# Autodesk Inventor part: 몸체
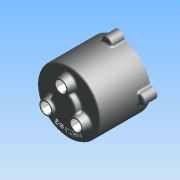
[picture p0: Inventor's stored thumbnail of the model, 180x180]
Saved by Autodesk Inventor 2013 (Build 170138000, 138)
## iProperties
Company: 한국ATC센터
Created: 2014-07
Part Number: 몸체
Document SubType Name: 모델링
Designer: KYOUNG IL JANG
Material: 알루미늄 6061
Mass: 475.555 g
Surface Area: 687.66 cm^2
Volume: 175.481 cm^3
Density: 2.71 g/cm^3
변환 표준: STEP AP214IS
파일 이름: C:\Users\SeoGD\Desktop\?쒗뿕\紐몄껜.stp
전처리기: Build: 253, Release: 2010 SP1 - Date: Wed 07/29/2009
전송 단위: 밀리미터
불확실성: 0.01
Author: KYOUNG IL JANG
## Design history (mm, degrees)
sketch "스케치2"
  geometry: C1 r 50 at (0, 0); 1 further point
  constraints: 1 centre point, 1 coincident
  dimensions: "d9" = 100 diameter of C1
extrude "돌출2" new body sketch "스케치2" distance "d10" = 80; taper "d11" = 0 deg
feature "쉘1" dims "d12" = 5
sketch "스케치3" dims "d13" = 55
  geometry: C1 r 7.5 at (0, 27.5); C2 r 12.5 at (0, 27.5); 2 further points
  constraints: 2 centre point, 2 coincident, 2 vertical alignment, 2 other
  dimensions: "d14" = 15 diameter of C1; "d15" = 25 diameter of C2
extrude "돌출3" join sketch "스케치3" distance "d16" = 12; taper "d17" = -10 deg
hole "구멍2" diameter "d20" = 15; stored, may be unused: countersink angle "d24" = 90 deg, drill point angle "d26" = 118 deg; dims "d18" = 10, "d19" = 10, "d21" = 6, "d22" = 4, "d23" = 2, "d25" = 15
chamfer "모따기1" distance "d27" = 1; stored, may be unused: second distance "d28" = 2, angle "d29" = 45 deg
sketch "스케치4"
  geometry: L1 (0, 0)-(0, 88); L2 (0, 70)-(13.16, 70); L3 (-45, 75)-(45, 75) reference; L4 (-50, 80)-(50, 80) reference; L5 (13.16, 70)-(14.5, 75); L6 (20, 80)-(20, 88); L7 (20, 88)-(0, 88); L8 (20, 80)-(14.5, 75)
  constraints: 12 end point, 3 point on line, 2 perpendicular, 1 vertical
  dimensions: "d34" = 40 diameter of L6 L1; "d35" = 105 deg angle of L5 L3; "d36" = 5 distance between parallel lines of L2 L3; "d37" = 8 distance between parallel lines of L7 L4; "d51" = 29 diameter of L5.end L1
revolve "회전1" sketch "스케치4" stored, may be unused: angle "d38" = 90 deg
hole "구멍3" diameter "d41" = 15; stored, may be unused: countersink angle "d45" = 90 deg, drill point angle "d47" = 0 deg; dims "d39" = 10, "d40" = 10, "d42" = 6, "d43" = 22, "d44" = 13, "d46" = 15
chamfer "모따기2" distance "d48" = 1; stored, may be unused: second distance "d49" = 2, angle "d50" = 45 deg
fillet "모깎기1" dims "d52" = 3
fillet "모깎기2" dims "d53" = 3, "d72" = 0.2
sketch "스케치5"
  geometry: A1 r 50 centre (0, 0) between (50, 0) and (-8.074, 49.344) reference; A2 r 8.5 centre (0, 52) between (8.074, 49.344) and (-8.074, 49.344); 1 further point
  constraints: 5 point on circle, 1 centre point, 1 horizontal alignment
  dimensions: "d54" = 90 deg dimension on point (0, 0) A2.centre A1.start; "d55" = 52 distance of A2.centre point (0, 0); "d56" = 17 diameter of A2
extrude "돌출4" join sketch "스케치5" distance "d57" = 20; taper "d58" = 0 deg
fillet "모깎기3" dims "d59" = 3
hole "구멍4" diameter "d62" = 4.134; stored, may be unused: countersink angle "d66" = 90 deg, drill point angle "d68" = 118 deg; dims "d60" = 10, "d61" = 10, "d63" = 12, "d64" = 22, "d65" = 13, "d67" = 15
sketch "스케치6"
  geometry: C1 r 47 at (0, 0) reference; C2 r 42.5 at (0, 0); 1 further point
  constraints: 1 centre point, 1 coincident, 1 other
  dimensions: "d73" = 85 diameter of C2
feature "엠보싱1" sketch "스케치6" dims "d74" = 1, "d75" = 0
node "솔리드1"
node "솔리드 본체"
node "곡면 본체"
pattern_circular "원형 패턴1" dims "d31" = 360 deg
pattern_circular "원형 패턴2" dims "d70" = 360 deg
node "솔리드2"
